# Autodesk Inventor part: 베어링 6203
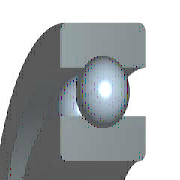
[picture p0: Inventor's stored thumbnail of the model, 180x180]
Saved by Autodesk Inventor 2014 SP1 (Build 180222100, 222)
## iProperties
IsCustomPart: 0
Created: 2016-04
Part Number: 베어링 6203
Material: 알루미늄 6061
Description: 깊은 그루브 볼 베어링
Document SubType Name: Modeling
Standard: KS B 2023
Designer: mdu
Standards Organization: KS
Language: ko-KR
Size Designation: 6203 - 17 x 40 x 12
Categories: <MemberInstance><Categories><Category DisplayName="샤프트 부품" InternalName="7f7aeb1f-a693-4053-b835-cee3144e0d98" Mnemonic="SHFT"><Category DisplayName="베어링" Inter
Density: 2.71 g/cm^3
Mass: 22.4044 g
Surface Area: 64.3582 cm^2
Volume: 8.26729 cm^3
Appearance: 알루미늄 - 평지
Author: mdu
Revision Number: 1
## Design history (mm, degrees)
sketch "스케치" dims "d0" = 5.98 (= -0.26 x WD + 0.26 x BD)
  geometry: L1 (3.01, 14.25)-(8.99, 14.25); L2 (6, 14.25)-(6, 11.26); L3 (6, 14.25)-(6, 17.24); L4 (3.778, 12.249)-(0, 12.249); L5 (0, 8.5)-(12, 8.5); L6 (3.778, 16.251)-(0, 16.251); L7 (0, 20)-(12, 20); L8 (12, 8.5)-(12, 12.249); L9 (8.222, 12.249)-(12, 12.249); L10 (8.222, 16.251)-(12, 16.251); L11 (12, 20)-(12, 16.251); L12 (-1.4, 0)-(8.4, 0) reference; L13 (0, -0.3)-(0, 5.3) reference
  constraints: 22 end point, 4 point on line, 2 collinear, 2 perpendicular, 2 symmetric about line, 1 midpoint, 1 parallel, 14 other
  dimensions: "d9" = 17 diameter of L5 L12 (= WD); "d11" = 40 diameter of L7 L12 (= BD); "d12" = 12 distance between parallel lines of L8 L13 (= KB); "d13" = 24.498 diameter of L9 L12 (= 0.326 x BD + 0.674 x WD)
revolve "본체" stored, may be unused: angle "d6" = 90 deg
revolve "볼" stored, may be unused: angle "d7" = 90 deg
pattern_circular "IDS_ARRAYBALL[SIMPL:T]" dims angle "d3" = 360 deg
body "Solid1"
fillet "모깎기1" dims "d1" = 0.6 (= KRS)
other parameters: "WD" = 17 [user parameter; used in 5 equation terms], "BD" = 40 [user parameter; used in 5 equation terms], "KB" = 12 [user parameter; used in 1 equation term], "KRS" = 0.6 [user parameter; used in 1 equation term], "d4" = 0, "d5" = 0, "d8" = 0, "d14" = 0, "d15" = 0, "BBA" = 0 [user parameter], "BC0" = 4750000 [user parameter], "BC" = 9560000 [user parameter], "WR" = 8.5 (= 0.5 x WD) [user parameter]
